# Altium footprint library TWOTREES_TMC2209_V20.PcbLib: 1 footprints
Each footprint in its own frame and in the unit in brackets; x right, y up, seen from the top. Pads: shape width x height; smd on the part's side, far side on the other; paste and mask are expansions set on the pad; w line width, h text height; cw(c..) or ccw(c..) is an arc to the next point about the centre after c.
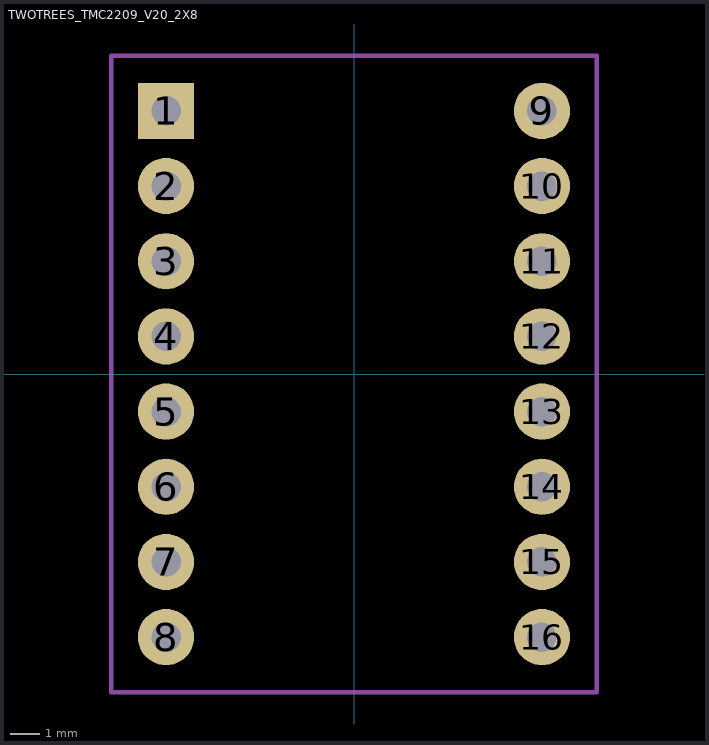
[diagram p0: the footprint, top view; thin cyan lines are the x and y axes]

## TWOTREES_TMC2209_V20_2X8 [mm] "TWOTREES TMC2209 V2.0; 2x8 sockets; nominal mechanical study Rev B; blue heatsink embedded"
height 22.315
pads (16):
  rect 1.9x1.9 hole 1: 1(-6.35,8.89)
  round 1.9 hole 1: 2(-6.35,6.35) 3(-6.35,3.81) 4(-6.35,1.27) 5(-6.35,-1.27) 6(-6.35,-3.81) 7(-6.35,-6.35) 8(-6.35,-8.89) 9(6.35,8.89) 10(6.35,6.35) 11(6.35,3.81) 12(6.35,1.27) 13(6.35,-1.27) 14(6.35,-3.81) 15(6.35,-6.35) 16(6.35,-8.89)
Mid20:
  lines w0.15: -7.62,-10.16 7.62,-10.16 7.62,10.16 -7.62,10.16 -7.62,-10.16
  text ".Designator" at -7.62,11.5 h1
  text "EN" at -5.1,8 h0.7
  text "VM" at 3.8,8 h0.7
Mech2:
  lines w0.15: -8.2,-10.75 8.2,-10.75 8.2,10.75 -8.2,10.75 -8.2,-10.75
3D body "TWOTREES_TMC2209_V20_Completo.step": height 22.31, standoff 0, extent -7.62,-10.16 7.62,10.16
